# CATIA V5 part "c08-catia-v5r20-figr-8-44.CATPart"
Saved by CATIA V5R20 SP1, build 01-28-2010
Part number: Part1
Bounding box of the stored display mesh (mm): x -50 to 50, y -50 to 50, z 0 to 25
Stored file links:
  D:\v5_r20\psrt_files_downloaded\c08-catia-v5r20-prt\c08-catia-v5r20-figr-8-44.CATPart
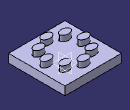
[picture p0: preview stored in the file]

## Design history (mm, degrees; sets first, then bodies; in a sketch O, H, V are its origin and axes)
Body1 (main body)
  Sketch1 on xy-plane, origin (0, 0, 0), H (1, 0, 0), V (0, 1, 0)
    line L1 (-50, 50) -> (50, 50)
    line L2 (50, 50) -> (50, -50)
    line L3 (50, -50) -> (-50, -50)
    line L4 (-50, -50) -> (-50, 50)
    axis line L5 (50, -50) -> (-50, 50)
    length L2 = 100
    length L3 = 100
    horizontal: L1 H, L3 H
    vertical: L2 V, L4 V
    midpoint: L5 O
  Pad1: profile Sketch1, direction (0, 0, 1), length 15
  Sketch2 on face of Pad1, origin (0, 0, 15), H (1, 0, 0), V (0, 1, 0)
    point P1 (0, -32.9864)
    ellipse A1 centre (0, -32.9864) semi-axes 9.9006, 6.5465 rotation 0
    point P2 (0, -26.4399)
    coincidence: P1 V, P2 V, A1 P2
  Pad2: profile Sketch2, direction (0, 0, 1), length 10
  CircPattern1: of Pad2, instances 8, angular step 45 {= 360.0*1 deg/CircPattern1.AngularNumber}, axis from edge of Sketch3
  Sketch3 on yz-plane, origin (0, 0, 0), H (0, 1, 0), V (0, 0, 1)
    line L1 (0, 0) -> (0, 18.4864)
    vertical: L1 V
